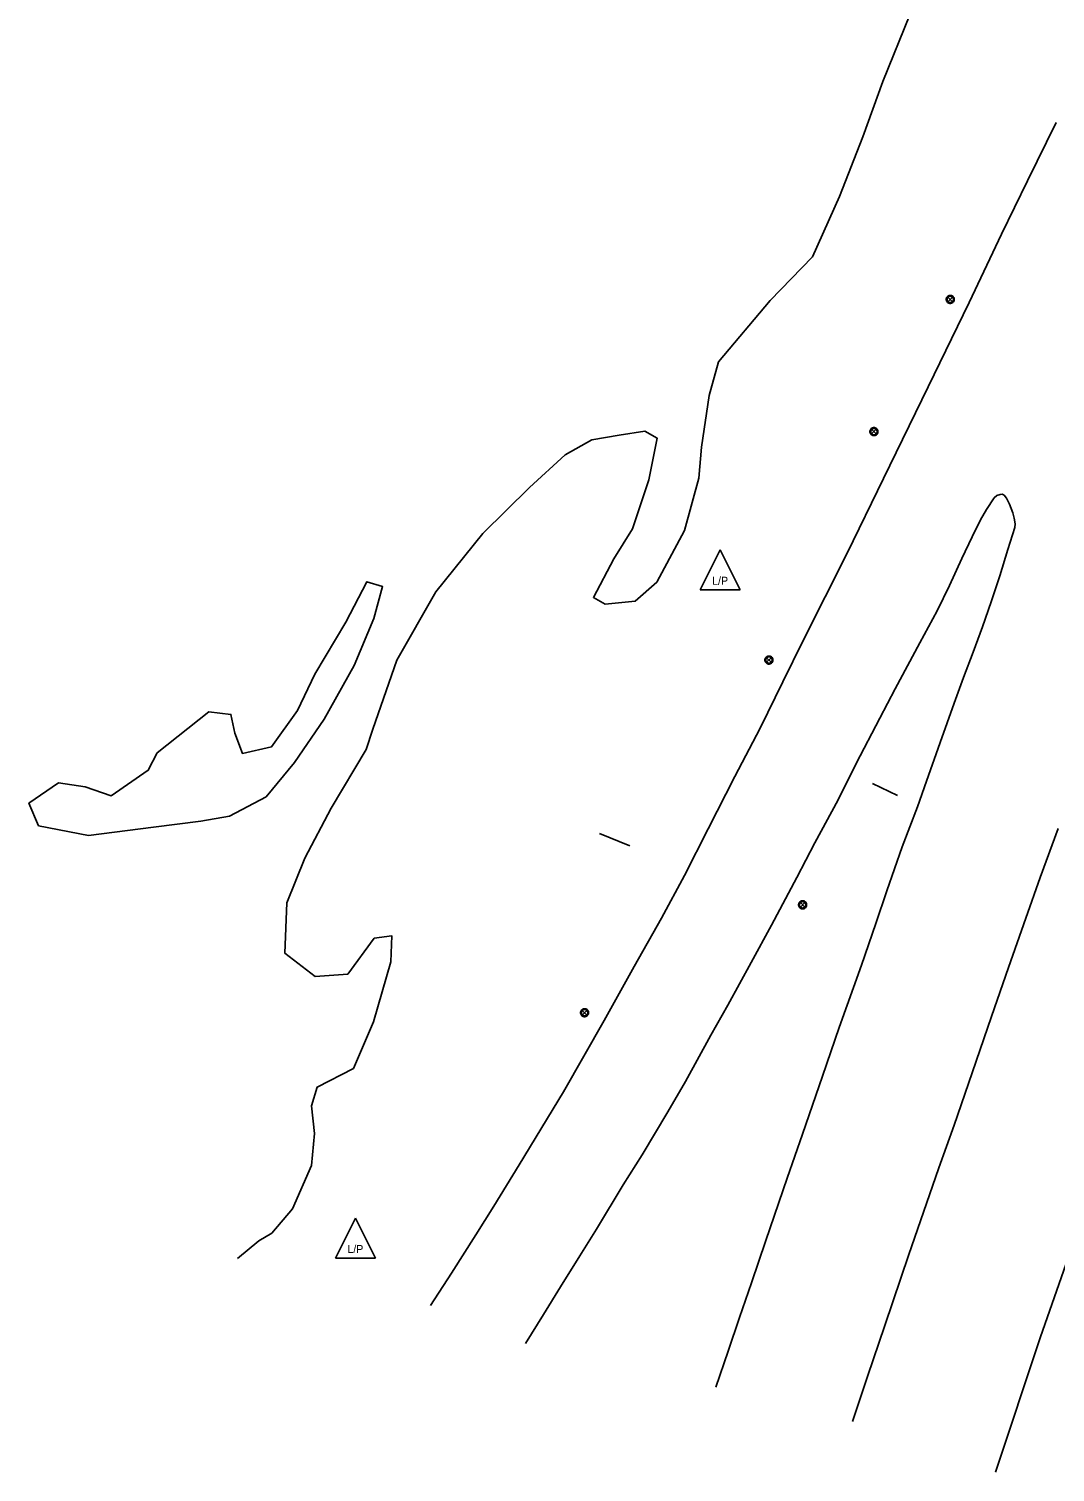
# Model space of a CAD drawing. Extents: x 2161152 to 2175754, y 602179 to 617749.
# Drawn here: x 2161151.6 to 2161408, y 602280.7 to 602641.4 of the extents above; entities that cross this region are included whole.
import ezdxf

# ---------------------------------------------------------------- set-up
doc = ezdxf.new("R2010")
doc.units = 0
for name, color, linetype in [('RD_EX_BldgApp_Post', 7, 'Continuous'), ('RD_EX_BldgApp_Sign', 7, 'Continuous'), ('RD_EX_Fence_Other', 7, 'Continuous'), ('RD_EX_Road', 7, 'Continuous'), ('RD_EX_UT', 7, 'Continuous'), ('RD_EX_VEG', 7, 'Continuous')]:
    doc.layers.add(name, color=color, linetype=linetype)

msp = doc.modelspace()

# ---------------------------------------------------------------- linework, layer by layer
at = {"layer": 'RD_EX_BldgApp_Post'}
for p, q in [((2161382.37, 602573.2), (2161381.24, 602574.33)), ((2161381.24, 602573.2), (2161382.37, 602574.33)), ((2161363.32, 602540.18), (2161362.18, 602541.31)), ((2161362.18, 602540.18), (2161363.32, 602541.31)), ((2161337.07, 602483.09), (2161335.93, 602484.23)), ((2161335.93, 602483.09), (2161337.07, 602484.23)), ((2161345.49, 602421.92), (2161344.36, 602423.06)), ((2161344.36, 602421.92), (2161345.49, 602423.06)), ((2161291.01, 602394.96), (2161289.88, 602396.1)), ((2161289.88, 602394.96), (2161291.01, 602396.1))]:
    msp.add_line(p, q, dxfattribs=at)
for points in [[(2161382.81, 602573.77), (2161382.8, 602573.92), (2161382.76, 602574.08), (2161382.68, 602574.25), (2161382.58, 602574.4), (2161382.44, 602574.54), (2161382.28, 602574.65), (2161382.09, 602574.73), (2161381.91, 602574.76), (2161381.72, 602574.77), (2161381.55, 602574.74), (2161381.39, 602574.68), (2161381.26, 602574.61), (2161381.13, 602574.51), (2161381.02, 602574.39), (2161380.92, 602574.23), (2161380.85, 602574.06), (2161380.81, 602573.87), (2161380.81, 602573.67), (2161380.85, 602573.48), (2161380.92, 602573.3), (2161381.02, 602573.15), (2161381.13, 602573.02), (2161381.26, 602572.93), (2161381.39, 602572.85), (2161381.55, 602572.8), (2161381.72, 602572.77), (2161381.91, 602572.77), (2161382.09, 602572.81), (2161382.28, 602572.88), (2161382.44, 602572.99), (2161382.58, 602573.13), (2161382.68, 602573.29), (2161382.76, 602573.45), (2161382.8, 602573.61), (2161382.81, 602573.77)], [(2161382.61, 602573.77), (2161382.6, 602573.89), (2161382.57, 602574.02), (2161382.51, 602574.15), (2161382.42, 602574.28), (2161382.31, 602574.39), (2161382.18, 602574.47), (2161382.04, 602574.53), (2161381.89, 602574.56), (2161381.74, 602574.57), (2161381.6, 602574.54), (2161381.48, 602574.5), (2161381.37, 602574.44), (2161381.27, 602574.36), (2161381.17, 602574.26), (2161381.1, 602574.14), (2161381.04, 602574), (2161381.01, 602573.85), (2161381.01, 602573.69), (2161381.04, 602573.53), (2161381.1, 602573.39), (2161381.17, 602573.27), (2161381.27, 602573.17), (2161381.37, 602573.09), (2161381.48, 602573.04), (2161381.6, 602572.99), (2161381.74, 602572.97), (2161381.89, 602572.97), (2161382.04, 602573), (2161382.18, 602573.06), (2161382.31, 602573.15), (2161382.42, 602573.26), (2161382.51, 602573.38), (2161382.57, 602573.51), (2161382.6, 602573.64), (2161382.61, 602573.77)], [(2161363.75, 602540.74), (2161363.74, 602540.9), (2161363.7, 602541.06), (2161363.63, 602541.22), (2161363.52, 602541.38), (2161363.39, 602541.52), (2161363.22, 602541.63), (2161363.04, 602541.7), (2161362.85, 602541.74), (2161362.67, 602541.74), (2161362.49, 602541.71), (2161362.34, 602541.66), (2161362.21, 602541.58), (2161362.08, 602541.49), (2161361.96, 602541.36), (2161361.86, 602541.21), (2161361.79, 602541.03), (2161361.75, 602540.84), (2161361.75, 602540.64), (2161361.79, 602540.45), (2161361.86, 602540.28), (2161361.96, 602540.12), (2161362.08, 602540), (2161362.21, 602539.9), (2161362.34, 602539.83), (2161362.49, 602539.77), (2161362.67, 602539.74), (2161362.85, 602539.75), (2161363.04, 602539.78), (2161363.22, 602539.86), (2161363.39, 602539.97), (2161363.52, 602540.11), (2161363.63, 602540.26), (2161363.7, 602540.43), (2161363.74, 602540.59), (2161363.75, 602540.74)], [(2161363.55, 602540.74), (2161363.54, 602540.87), (2161363.51, 602541), (2161363.45, 602541.13), (2161363.37, 602541.25), (2161363.26, 602541.36), (2161363.13, 602541.45), (2161362.98, 602541.51), (2161362.83, 602541.54), (2161362.68, 602541.54), (2161362.55, 602541.52), (2161362.42, 602541.47), (2161362.32, 602541.42), (2161362.21, 602541.34), (2161362.12, 602541.24), (2161362.04, 602541.12), (2161361.98, 602540.98), (2161361.95, 602540.82), (2161361.95, 602540.66), (2161361.98, 602540.51), (2161362.04, 602540.37), (2161362.12, 602540.25), (2161362.21, 602540.15), (2161362.32, 602540.07), (2161362.42, 602540.01), (2161362.55, 602539.97), (2161362.68, 602539.94), (2161362.83, 602539.94), (2161362.98, 602539.97), (2161363.13, 602540.04), (2161363.26, 602540.12), (2161363.37, 602540.23), (2161363.45, 602540.36), (2161363.51, 602540.49), (2161363.54, 602540.62), (2161363.55, 602540.74)], [(2161337.5, 602483.66), (2161337.49, 602483.82), (2161337.45, 602483.98), (2161337.38, 602484.14), (2161337.28, 602484.3), (2161337.14, 602484.44), (2161336.97, 602484.55), (2161336.79, 602484.62), (2161336.6, 602484.66), (2161336.42, 602484.66), (2161336.25, 602484.63), (2161336.09, 602484.58), (2161335.96, 602484.5), (2161335.83, 602484.41), (2161335.71, 602484.28), (2161335.61, 602484.13), (2161335.54, 602483.95), (2161335.5, 602483.76), (2161335.5, 602483.56), (2161335.54, 602483.37), (2161335.61, 602483.19), (2161335.71, 602483.04), (2161335.83, 602482.92), (2161335.96, 602482.82), (2161336.09, 602482.75), (2161336.25, 602482.69), (2161336.42, 602482.66), (2161336.6, 602482.66), (2161336.79, 602482.7), (2161336.97, 602482.78), (2161337.14, 602482.89), (2161337.28, 602483.02), (2161337.38, 602483.18), (2161337.45, 602483.34), (2161337.49, 602483.51), (2161337.5, 602483.66)], [(2161337.3, 602483.66), (2161337.29, 602483.78), (2161337.26, 602483.92), (2161337.21, 602484.05), (2161337.12, 602484.17), (2161337.01, 602484.28), (2161336.88, 602484.37), (2161336.73, 602484.43), (2161336.58, 602484.46), (2161336.43, 602484.46), (2161336.3, 602484.44), (2161336.17, 602484.39), (2161336.07, 602484.33), (2161335.97, 602484.26), (2161335.87, 602484.16), (2161335.79, 602484.04), (2161335.73, 602483.89), (2161335.7, 602483.74), (2161335.7, 602483.58), (2161335.73, 602483.43), (2161335.79, 602483.29), (2161335.87, 602483.17), (2161335.97, 602483.07), (2161336.07, 602482.99), (2161336.17, 602482.93), (2161336.3, 602482.89), (2161336.43, 602482.86), (2161336.58, 602482.86), (2161336.73, 602482.89), (2161336.88, 602482.95), (2161337.01, 602483.04), (2161337.12, 602483.15), (2161337.21, 602483.28), (2161337.26, 602483.41), (2161337.29, 602483.54), (2161337.3, 602483.66)], [(2161345.92, 602422.49), (2161345.91, 602422.64), (2161345.87, 602422.81), (2161345.8, 602422.97), (2161345.7, 602423.13), (2161345.56, 602423.26), (2161345.39, 602423.37), (2161345.21, 602423.45), (2161345.02, 602423.49), (2161344.84, 602423.49), (2161344.67, 602423.46), (2161344.51, 602423.4), (2161344.38, 602423.33), (2161344.25, 602423.23), (2161344.13, 602423.11), (2161344.04, 602422.96), (2161343.96, 602422.78), (2161343.92, 602422.59), (2161343.92, 602422.39), (2161343.96, 602422.2), (2161344.04, 602422.02), (2161344.13, 602421.87), (2161344.25, 602421.74), (2161344.38, 602421.65), (2161344.51, 602421.57), (2161344.67, 602421.52), (2161344.84, 602421.49), (2161345.02, 602421.49), (2161345.21, 602421.53), (2161345.39, 602421.6), (2161345.56, 602421.71), (2161345.7, 602421.85), (2161345.8, 602422.01), (2161345.87, 602422.17), (2161345.91, 602422.33), (2161345.92, 602422.49)], [(2161345.72, 602422.49), (2161345.71, 602422.61), (2161345.68, 602422.74), (2161345.63, 602422.87), (2161345.54, 602423), (2161345.43, 602423.11), (2161345.3, 602423.2), (2161345.15, 602423.26), (2161345, 602423.29), (2161344.86, 602423.29), (2161344.72, 602423.26), (2161344.59, 602423.22), (2161344.49, 602423.16), (2161344.39, 602423.08), (2161344.29, 602422.98), (2161344.21, 602422.86), (2161344.16, 602422.72), (2161344.12, 602422.57), (2161344.12, 602422.41), (2161344.16, 602422.26), (2161344.21, 602422.11), (2161344.29, 602421.99), (2161344.39, 602421.89), (2161344.49, 602421.82), (2161344.59, 602421.76), (2161344.72, 602421.71), (2161344.86, 602421.69), (2161345, 602421.69), (2161345.15, 602421.72), (2161345.3, 602421.78), (2161345.43, 602421.87), (2161345.54, 602421.98), (2161345.63, 602422.1), (2161345.68, 602422.23), (2161345.71, 602422.37), (2161345.72, 602422.49)], [(2161291.45, 602395.53), (2161291.44, 602395.69), (2161291.4, 602395.85), (2161291.32, 602396.01), (2161291.22, 602396.17), (2161291.08, 602396.3), (2161290.92, 602396.41), (2161290.73, 602396.49), (2161290.55, 602396.53), (2161290.36, 602396.53), (2161290.19, 602396.5), (2161290.03, 602396.45), (2161289.9, 602396.37), (2161289.77, 602396.28), (2161289.66, 602396.15), (2161289.56, 602396), (2161289.49, 602395.82), (2161289.45, 602395.63), (2161289.45, 602395.43), (2161289.49, 602395.24), (2161289.56, 602395.06), (2161289.66, 602394.91), (2161289.77, 602394.79), (2161289.9, 602394.69), (2161290.03, 602394.62), (2161290.19, 602394.56), (2161290.36, 602394.53), (2161290.55, 602394.53), (2161290.73, 602394.57), (2161290.92, 602394.65), (2161291.08, 602394.76), (2161291.22, 602394.89), (2161291.32, 602395.05), (2161291.4, 602395.21), (2161291.44, 602395.38), (2161291.45, 602395.53)], [(2161291.25, 602395.53), (2161291.24, 602395.65), (2161291.21, 602395.78), (2161291.15, 602395.92), (2161291.06, 602396.04), (2161290.95, 602396.15), (2161290.82, 602396.24), (2161290.68, 602396.3), (2161290.53, 602396.33), (2161290.38, 602396.33), (2161290.24, 602396.31), (2161290.12, 602396.26), (2161290.01, 602396.2), (2161289.91, 602396.13), (2161289.81, 602396.03), (2161289.74, 602395.9), (2161289.68, 602395.76), (2161289.65, 602395.61), (2161289.65, 602395.45), (2161289.68, 602395.3), (2161289.74, 602395.16), (2161289.81, 602395.03), (2161289.91, 602394.93), (2161290.01, 602394.86), (2161290.12, 602394.8), (2161290.24, 602394.76), (2161290.38, 602394.73), (2161290.53, 602394.73), (2161290.68, 602394.76), (2161290.82, 602394.82), (2161290.95, 602394.91), (2161291.06, 602395.02), (2161291.15, 602395.15), (2161291.21, 602395.28), (2161291.24, 602395.41), (2161291.25, 602395.53)]]:
    msp.add_lwpolyline(points, dxfattribs=at)
at = {"layer": 'RD_EX_BldgApp_Sign'}
for p, q in [((2161362.38, 602452.81), (2161368.63, 602449.79)), ((2161301.75, 602437.24), (2161294.2, 602440.33))]:
    msp.add_line(p, q, dxfattribs=at)
at = {"layer": 'RD_EX_Fence_Other'}
msp.add_lwpolyline([(2161393.1, 602280.73), (2161404.32, 602314.28), (2161421.35, 602363.12), (2161445.71, 602432.45), (2161466.82, 602491.42), (2161492.35, 602560.11), (2161518.45, 602628.79), (2161543.97, 602694.29), (2161567.05, 602752.08), (2161594.98, 602821.59), (2161625.11, 602893.85), (2161655.74, 602966.15), (2161670.93, 603001.3), (2161686.85, 603037.69), (2161703.84, 603076.57), (2161723.47, 603119.8), (2161742.31, 603159.17), (2161753.57, 603183.42), (2161762.92, 603204.09), (2161772.85, 603227.48)], dxfattribs=at)
at = {"layer": 'RD_EX_Road'}
for points in [[(2161251.97, 602322.34), (2161257.2, 602330.47), (2161263.27, 602340.03), (2161267.79, 602347.16), (2161274.11, 602357.54), (2161285.22, 602375.79), (2161295.34, 602393.62), (2161302.82, 602407.12), (2161309.65, 602419.19), (2161315.43, 602429.78), (2161321.37, 602441.45), (2161327.96, 602454.59), (2161334.33, 602466.64), (2161340.02, 602478.23), (2161345.09, 602488.53), (2161356.04, 602510.35), (2161365.13, 602529.06), (2161376.26, 602551.95), (2161386.58, 602572.97), (2161394.62, 602590.05), (2161401.09, 602603.41), (2161408.31, 602617.97)], [(2161275.67, 602312.88), (2161280.19, 602320.16), (2161284.4, 602327.01), (2161289.29, 602334.82), (2161293.42, 602341.47), (2161300.06, 602352.53), (2161304.84, 602360.03), (2161311.25, 602370.8), (2161315.66, 602378.38), (2161322.03, 602389.92), (2161326.22, 602397.41), (2161332.05, 602408.06), (2161337.16, 602417.37), (2161343.5, 602429.28), (2161347.97, 602437.95), (2161353.81, 602448.76), (2161358.27, 602457.79), (2161364.2, 602469.17), (2161368.07, 602476.48), (2161374.22, 602487.93), (2161378.55, 602495.93), (2161381.62, 602502.31), (2161384.72, 602509.06), (2161387.28, 602514.41), (2161389.35, 602518.71), (2161390.86, 602521.31), (2161392.82, 602524.15), (2161393.48, 602524.78), (2161394.25, 602525.06), (2161394.82, 602525.11), (2161395.26, 602524.85), (2161395.88, 602524.09), (2161396.62, 602522.64), (2161397.47, 602520.48), (2161397.77, 602519.11), (2161398.04, 602517.69), (2161397.97, 602516.8), (2161396.22, 602511.32), (2161394.21, 602504.66), (2161392.06, 602498.19), (2161389.9, 602491.96), (2161387.55, 602485.6), (2161385.11, 602479.31), (2161382.79, 602472.84), (2161379.28, 602463.04), (2161375.87, 602453.37), (2161373.64, 602446.99), (2161371.7, 602441.96), (2161369.83, 602436.95), (2161365.98, 602426.01), (2161363.22, 602417.8), (2161359.61, 602407.4), (2161354.08, 602391.86), (2161349.86, 602379.64), (2161344.91, 602365.22), (2161341.08, 602354.2), (2161335.71, 602338.62), (2161332.12, 602328.04), (2161329.16, 602319.37), (2161326.35, 602310.94), (2161323.28, 602301.97)], [(2161357.39, 602293.35), (2161361.18, 602304.64), (2161365.47, 602317.36), (2161371.47, 602335.1), (2161375.13, 602345.69), (2161378.99, 602356.75), (2161382.76, 602367.42), (2161386.34, 602377.83), (2161392.14, 602394.61), (2161396.41, 602406.83), (2161400.74, 602419.17), (2161404.32, 602429.36), (2161408.75, 602441.58)]]:
    msp.add_lwpolyline(points, dxfattribs=at)
at = {"layer": 'RD_EX_UT'}
for p, q in [((2161319.3, 602501.19), (2161324.3, 602511.19)), ((2161324.3, 602511.19), (2161329.3, 602501.19)), ((2161319.3, 602501.19), (2161329.3, 602501.19)), ((2161228.18, 602334.2), (2161233.18, 602344.2)), ((2161233.18, 602344.2), (2161238.18, 602334.2)), ((2161228.18, 602334.2), (2161238.18, 602334.2))]:
    msp.add_line(p, q, dxfattribs=at)
at = {"layer": 'RD_EX_VEG'}
for points in [[(2161371.68, 602644.89), (2161364.94, 602628.19), (2161359.99, 602614.4), (2161354.17, 602599.51), (2161347.43, 602584.42), (2161336.84, 602573.53), (2161323.9, 602558.19), (2161321.6, 602549.79), (2161319.66, 602536.81), (2161319.01, 602529.13), (2161315.43, 602516.05), (2161308.53, 602503.12), (2161303.06, 602498.37), (2161295.62, 602497.62), (2161292.67, 602499.31), (2161297.79, 602508.98), (2161302.41, 602516.41), (2161306.47, 602528.71), (2161308.57, 602539.13), (2161305.52, 602540.85), (2161299.08, 602539.84), (2161292.3, 602538.7), (2161285.59, 602534.91), (2161276.69, 602526.8), (2161265.04, 602515.28), (2161253.31, 602500.69), (2161243.52, 602483.6), (2161237.54, 602466.42), (2161235.84, 602461.31), (2161227.11, 602446.62), (2161220.59, 602434.19), (2161216.01, 602422.97), (2161215.58, 602410.41), (2161223.14, 602404.6), (2161231.26, 602405.14), (2161237.88, 602414.16), (2161242.3, 602414.74), (2161242.04, 602408.25), (2161237.67, 602393.24), (2161232.73, 602381.62), (2161223.62, 602376.95), (2161222.22, 602372.25), (2161222.97, 602365.32), (2161222.23, 602357.32), (2161217.44, 602346.52), (2161212.29, 602340.45), (2161209.09, 602338.51), (2161203.73, 602334.12)], [(2161183.65, 602460.48), (2161181.44, 602456.1), (2161172.17, 602449.71), (2161165.63, 602451.98), (2161159.02, 602452.97), (2161151.59, 602447.86), (2161154.03, 602442.26), (2161166.52, 602439.79), (2161182.76, 602441.89), (2161194.53, 602443.43), (2161201.74, 602444.66), (2161210.85, 602449.51), (2161218, 602458.03), (2161225.39, 602468.92), (2161232.85, 602482.32), (2161237.78, 602494.07), (2161239.98, 602502), (2161236.08, 602503.2), (2161230.82, 602493.1), (2161223.05, 602480.15), (2161218.7, 602471.07), (2161212.23, 602461.99), (2161204.94, 602460.33), (2161203.08, 602465.4), (2161202.06, 602470.07), (2161196.54, 602470.71), (2161183.65, 602460.48)]]:
    msp.add_lwpolyline(points, dxfattribs=at)

# ---------------------------------------------------------------- texts
at = {"layer": 'RD_EX_UT'}
for p in [(2161322.3, 602502.47), (2161231.17, 602335.48)]:
    msp.add_text('L/P', height=2, dxfattribs=at).set_placement(p)

doc.saveas('drawing.dxf')
